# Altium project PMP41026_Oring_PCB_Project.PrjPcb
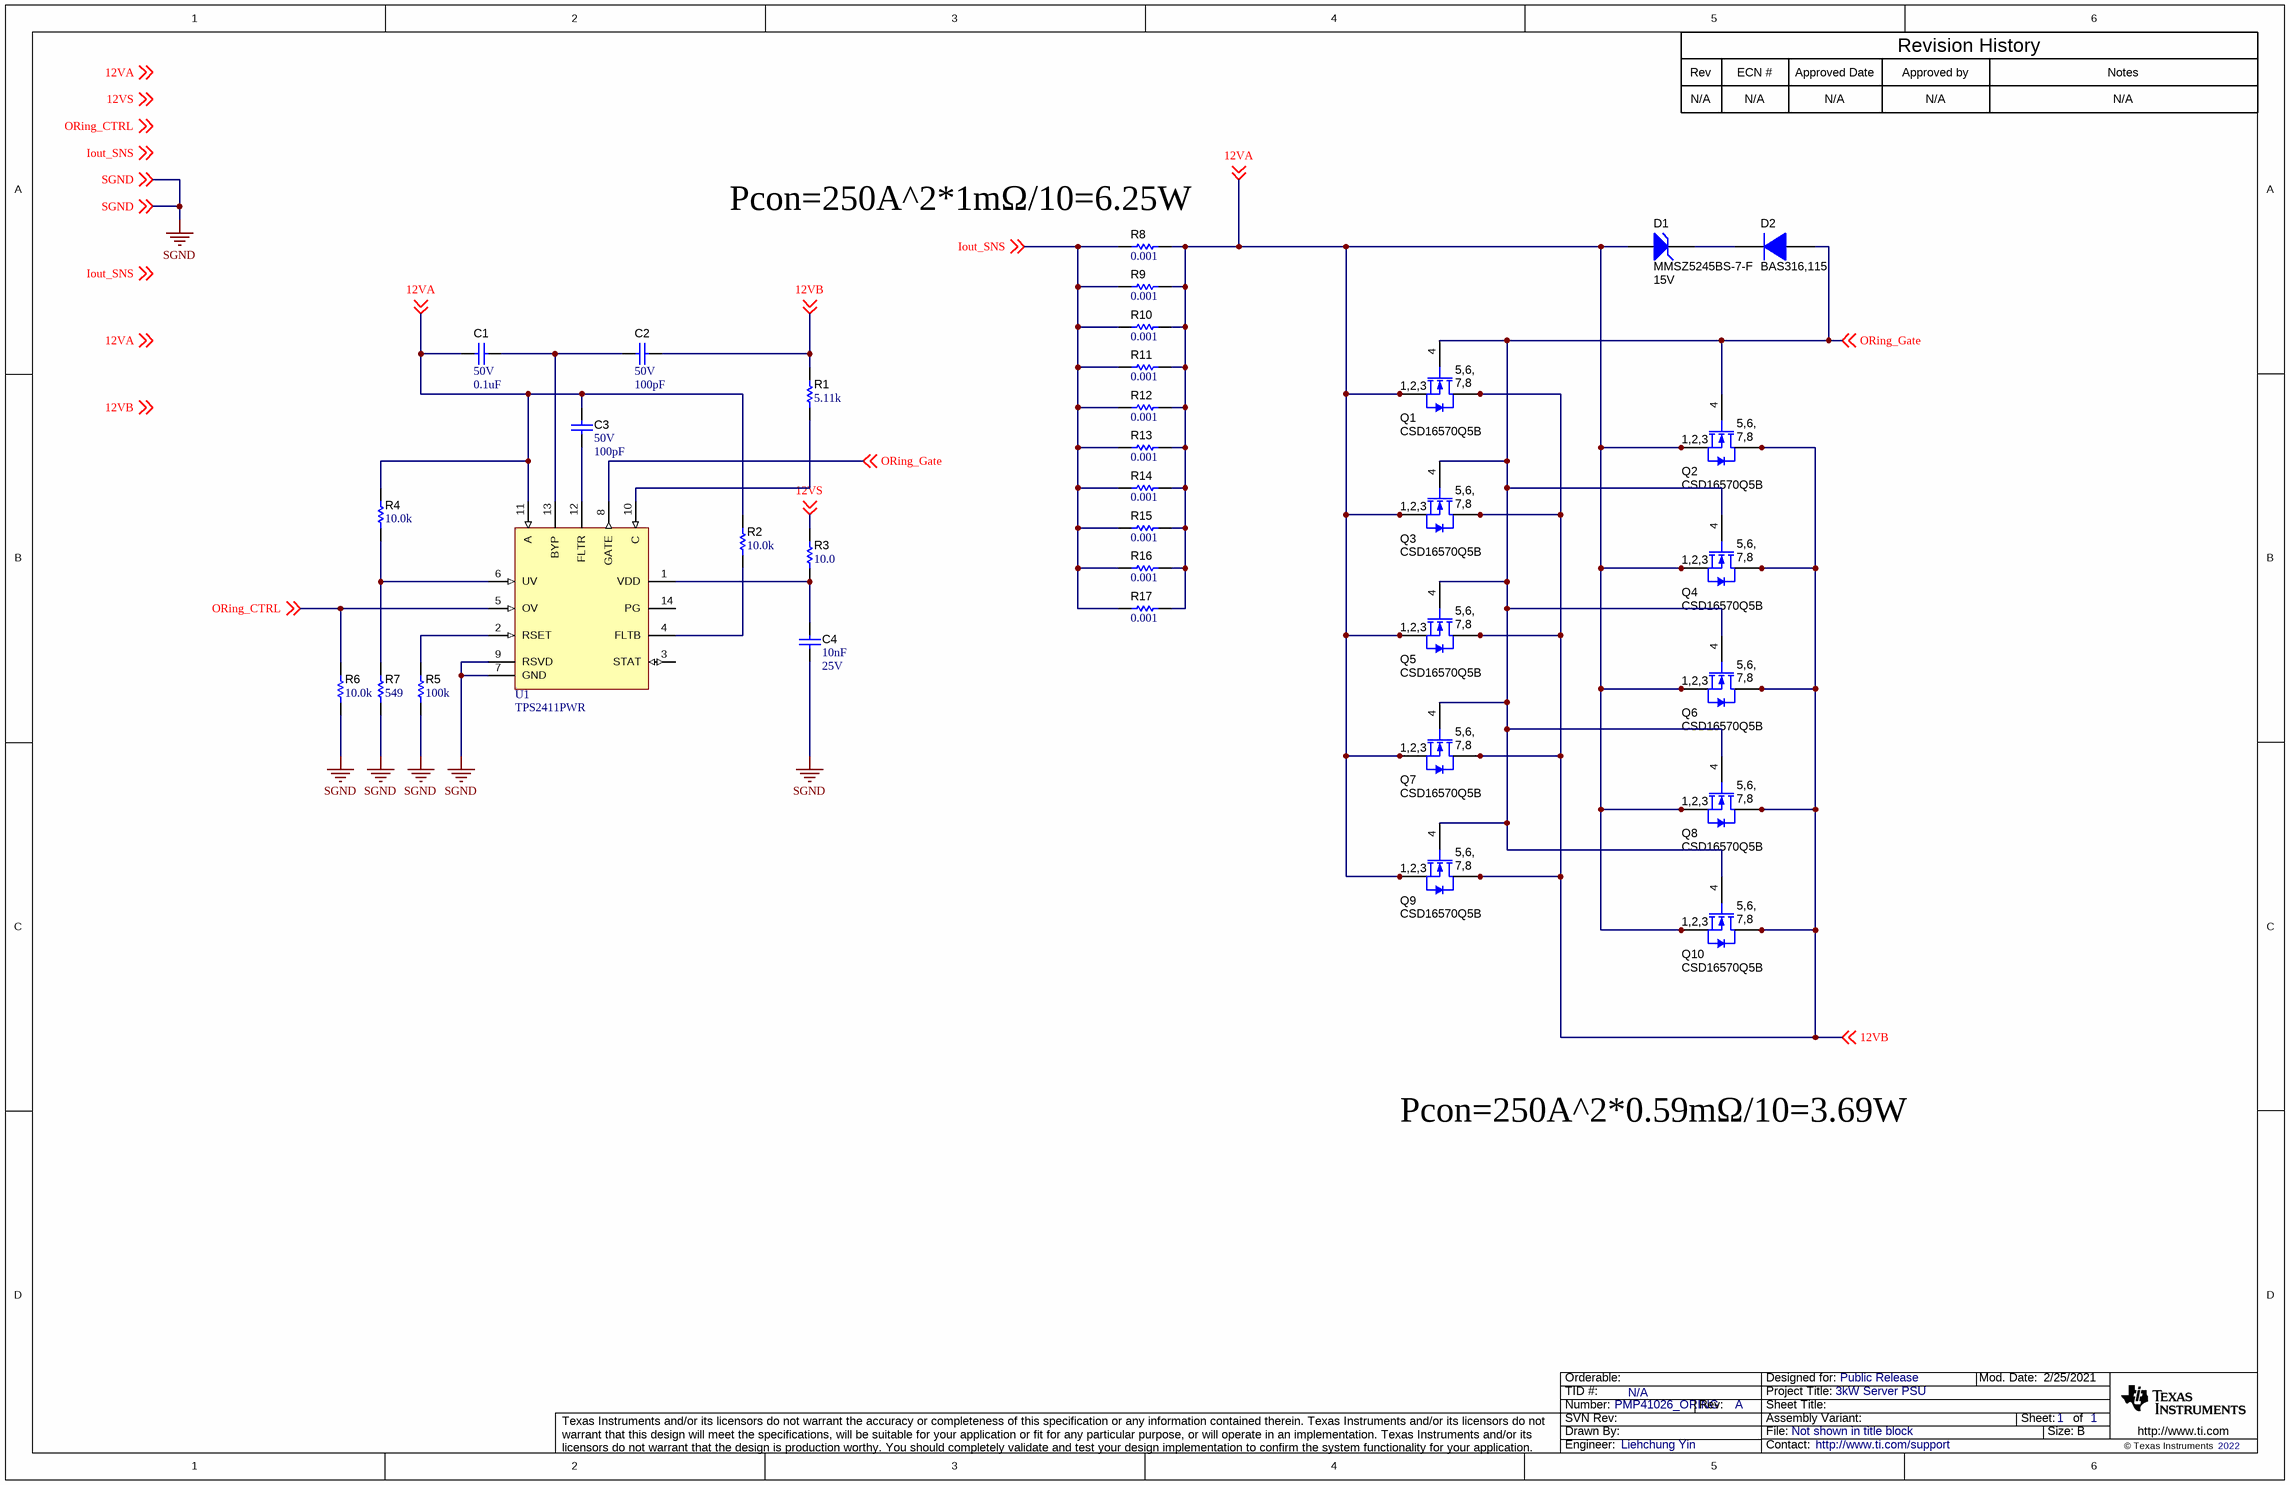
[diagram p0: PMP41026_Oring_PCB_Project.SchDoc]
TID: N/A; TechSupport: http://www.ti.com/support; SCH_Rev: A; PRJ_Title: 3kW Server PSU; PRJ_Number: PMP41026_ORING; PRJ_Engineer: Liehchung Yin; PRJ_Customer: Public Release; PCB_Rev: A; PCB_Layout: B. Lough/S. Yu; CopyrightYear: 2022
1 sheet, 34 parts. Net scope: global (net labels, ports and power ports of the same name join across sheets).
Board file: PMP41026_Oring_PCB_Project.PcbDoc

## Sheet PMP41026_Oring_PCB_Project.SchDoc
size 431 x 279 mm; Date: Not shown in title block; ApprovedBy: Not shown in title block; CheckedBy: Not shown in title block; Author: Not shown in title block; CompanyName: Not shown in title block; Engineer: Not shown in title block; Organization: Not shown in title block; Address1: Not shown in title block; Address2: Not shown in title block; Address3: Not shown in title block; Address4: Not shown in title block; DocumentNumber: 1; Revision: Use project parameter SCH_Rev; SheetNumber: 1; SheetTotal: 1; PageSetup: Record=PageOptions¦CenterHorizontal=True¦CenterVertical=True¦PrintScale=1.00¦XCorrection=1.00¦YCorrection=1.00¦PrintKind=0¦BorderSize=5000000¦LeftOffset=0¦BottomOffset=0¦Orientation=2¦PaperLength=1000¦PaperWidth=1000¦Scale=100¦PaperSource=15¦PrintQuality=600¦MediaType=1¦DitherType=10¦PaperKind=Letter¦PrintScaleMode=1

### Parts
C1  VDC_V: 50V  ValueDisplayed: 0.1uF  [0603L]  (hidden comment: C1608X5R1H104K080AA)
C2  VDC_V: 50V  ValueDisplayed: 100pF  [0603L]  (hidden comment: C0603C101J5GACTU)
C3  VDC_V: 50V  ValueDisplayed: 100pF  [0603L]  (hidden comment: C0603C101J5GACTU)
C4  Cap_F: 10nF  VDC_V: 25V  [0603L]  (hidden comment: GRM188R71E103KA01D)
D1  MMSZ5245BS-7-F  value 15V  [SOD-323]
D2  BAS316,115  [SOD-323]
Q1  CSD16570Q5B  [DNK0008A]
Q2  CSD16570Q5B  [DNK0008A]
Q3  CSD16570Q5B  [DNK0008A]
Q4  CSD16570Q5B  [DNK0008A]
Q5  CSD16570Q5B  [DNK0008A]
Q6  CSD16570Q5B  [DNK0008A]
Q7  CSD16570Q5B  [DNK0008A]
Q8  CSD16570Q5B  [DNK0008A]
Q9  CSD16570Q5B  [DNK0008A]
Q10  CSD16570Q5B  [DNK0008A]
R1  ValueDisplayed: 5.11k  [0402L]  (hidden comment: CRCW04025K11FKED)
R2  ValueDisplayed: 10.0k  [0402L]  (hidden comment: RC0402FR-0710KL)
R3  ValueDisplayed: 10.0  [0402L]  (hidden comment: MCR01MZPF10R0)
R4  ValueDisplayed: 10.0k  [0402L]  (hidden comment: RC0402FR-0710KL)
R5  ValueDisplayed: 100k  [0402L]  (hidden comment: RC0402FR-07100KL)
R6  ValueDisplayed: 10.0k  [0402L]  (hidden comment: RC0402FR-0710KL)
R7  ValueDisplayed: 549  [0402L]  (hidden comment: CRCW0402549RFKED)
R8  ValueDisplayed: 0.001  [WSLP2010-001]  (hidden comment: WSLP20101L000FEA)
R9  ValueDisplayed: 0.001  [WSLP2010-001]  (hidden comment: WSLP20101L000FEA)
R10  ValueDisplayed: 0.001  [WSLP2010-001]  (hidden comment: WSLP20101L000FEA)
R11  ValueDisplayed: 0.001  [WSLP2010-001]  (hidden comment: WSLP20101L000FEA)
R12  ValueDisplayed: 0.001  [WSLP2010-001]  (hidden comment: WSLP20101L000FEA)
R13  ValueDisplayed: 0.001  [WSLP2010-001]  (hidden comment: WSLP20101L000FEA)
R14  ValueDisplayed: 0.001  [WSLP2010-001]  (hidden comment: WSLP20101L000FEA)
R15  ValueDisplayed: 0.001  [WSLP2010-001]  (hidden comment: WSLP20101L000FEA)
R16  ValueDisplayed: 0.001  [WSLP2010-001]  (hidden comment: WSLP20101L000FEA)
R17  ValueDisplayed: 0.001  [WSLP2010-001]  (hidden comment: WSLP20101L000FEA)
U1  TPS2411PWR  [PW0014A_L]

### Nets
SGND: C4.2 R5.1 R6.1 R7.1 U1.7(GND) U1.9(RSVD) ; off-sheet SGND
12VA: C1.2 C3.1 D1.2(A) Q1.1(S) Q1.2(S) Q1.3(S) Q2.1(S) Q2.2(S) Q2.3(S) Q3.1(S) Q3.2(S) Q3.3(S) Q4.1(S) Q4.2(S) Q4.3(S) Q5.1(S) Q5.2(S) Q5.3(S) Q6.1(S) Q6.2(S) Q6.3(S) Q7.1(S) Q7.2(S) Q7.3(S) Q8.1(S) Q8.2(S) Q8.3(S) Q9.1(S) Q9.2(S) Q9.3(S) Q10.1(S) Q10.2(S) Q10.3(S) R2.2 R4.2 R8.2 R9.2 R10.2 R11.2 R12.2 R13.2 R14.2 R15.2 R16.2 R17.2 U1.11(A) ; off-sheet 12VA
12VB: C2.1 Q1.5(D) Q1.6(D) Q1.7(D) Q1.8(D) Q1.9(D) Q2.5(D) Q2.6(D) Q2.7(D) Q2.8(D) Q2.9(D) Q3.5(D) Q3.6(D) Q3.7(D) Q3.8(D) Q3.9(D) Q4.5(D) Q4.6(D) Q4.7(D) Q4.8(D) Q4.9(D) Q5.5(D) Q5.6(D) Q5.7(D) Q5.8(D) Q5.9(D) Q6.5(D) Q6.6(D) Q6.7(D) Q6.8(D) Q6.9(D) Q7.5(D) Q7.6(D) Q7.7(D) Q7.8(D) Q7.9(D) Q8.5(D) Q8.6(D) Q8.7(D) Q8.8(D) Q8.9(D) Q9.5(D) Q9.6(D) Q9.7(D) Q9.8(D) Q9.9(D) Q10.5(D) Q10.6(D) Q10.7(D) Q10.8(D) Q10.9(D) R1.2 ; off-sheet 12VB
12VS: R3.2 ; off-sheet 12VS
Iout_SNS: R8.1 R9.1 R10.1 R11.1 R12.1 R13.1 R14.1 R15.1 R16.1 R17.1 ; off-sheet Iout_SNS
ORing_CTRL: R6.2 U1.5(OV) ; off-sheet ORing_CTRL
ORing_Gate: D2.2(A) Q1.4(G) Q2.4(G) Q3.4(G) Q4.4(G) Q5.4(G) Q6.4(G) Q7.4(G) Q8.4(G) Q9.4(G) Q10.4(G) U1.8(GATE) ; off-sheet ORing_Gate
NetC1_1: C1.1 C2.2 U1.13(BYP)
NetC3_2: C3.2 U1.12(FLTR)
NetC4_1: C4.1 R3.1 U1.1(VDD)
NetD1_1: D1.1(K) D2.1(K)
NetR1_1: R1.1 U1.10(C)
NetR2_1: R2.1 U1.4(FLTB)
NetR4_1: R4.1 R7.2 U1.6(UV)
NetR5_2: R5.2 U1.2(RSET)

Not connected (* = marked no-connect by the designer): U1 3(STAT) 14(PG)

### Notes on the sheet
- Rev
- N/A
- ECN #
- Approved Date
- Approved by
- Revision History
- Notes
- (near R8) Pcon=250A^2*1mΩ/10=6.25W
- Pcon=250A^2*0.59mΩ/10=3.69W
- Labels drawn without touching a wire or pin: 12VA, 12VB, 12VS, Iout_SNS, ORing_CTRL

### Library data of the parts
C1 = CMP-0007010-5: CAP, CERM, 0.1 uF, 50 V, +/- 10%, X5R, 0603; Manufacturer: TDK; TaMin_C: -55°C; ESR_ohm: 0.0296; Polarized: N; SizeAreaWB_mm2: 4.68; Value1: 0.0296 ohm; U/M: EA; Value: 0.1uF; TaMax_C: 85°C; SizeZ_mm: 1; SizeX_mm: 1.6; SizeY_mm: 0.8; Cap_Case: 0603; SizeArea_mm2: 1.28; Cap_F: 100nF; IRMS_A: 9.7199dA; AEC Category: Q200
C2 C3 = CMP-0006841-4: CAP, CERM, 100 pF, 50 V, +/- 5%, C0G/NP0, 0603; Manufacturer: Kemet; TaMin_C: -55°C; Polarized: N; SizeAreaWB_mm2: 4.68; Value1: Unknown; U/M: EA; Value: 100pF; TaMax_C: 125°C; SizeZ_mm: 1; SizeX_mm: 1.6; SizeY_mm: 0.8; Cap_Case: 0603; SizeArea_mm2: 1.28; AEC Category: Q200
C4 = CMP-0007403-4: CAP, CERM, 0.01 uF, 25 V, +/- 10%, X7R, 0603; Manufacturer: MuRata; TaMin_C: -55°C; Polarized: N; SizeAreaWB_mm2: 4.68; Value1: Unknown; U/M: EA; Value: 0.01uF; TaMax_C: 125°C; SizeZ_mm: 1; SizeX_mm: 1.6; SizeY_mm: 0.8; Cap_Case: 0603; SizeArea_mm2: 1.28; AEC Category: Q200
D1 = CMP-0005833-4: Diode, Zener, 15 V, 200 mW, SOD-323; Manufacturer: Diodes Inc.; SizeY_mm: 1.35; RJA_CperW: 350; SizeX_mm: 2.7; AEC Category: Q101; SizeAreaWB_mm2: 8.695; SizeZ_mm: 1; Power_W: 200mW; SizeArea_mm2: 3.645; Value1: 0.2W
D2 = CMP-0029006-2: Diode, Ultrafast, 100 V, 0.25 A, SOD-323; Manufacturer: Nexperia; SizeY_mm: 1.35; Value1: 0.25A; SizeAreaWB_mm2: 8.695; SizeZ_mm: 1; Io_A: 250mA; Value2: 1.4V; SizeX_mm: 2.7; Green_REACh: Incomplete; TJmax_C: 150°C; Green_Lifecycle: Not Set; Vr_V: 100V; AEC Category: Q101; Value: 100V; SizeArea_mm2: 3.645
Q1-Q10 = CMP-0000274-2: MOSFET, N-CH, 25 V, 100 A, DNK0008A (VSON-CLIP-8); Alternate Manufacturer: None; Manufacturer: Texas Instruments; SizeZ_mm: 1; ChType: N; Value2: 192 nC; Value1: 0; VdsMax_V: 25V; SizeX_mm: 6; SizeY_mm: 5; Vgs_V: 20V; Value: 25V; Rdson45_ohm: 800µ; SizeArea_mm2: 30; AEC Category: Q101; IdsMax_A: 100A; SizeAreaWB_mm2: 56; U/M: EA; QgTyp_nC: 192
R1 = CMP-0026463-2: RES, 5.11 k, 1%, 0.063 W, AEC-Q200 Grade 0, 0402; Manufacturer: Vishay-Dale; Power_W: 63mW; TempCo: 100 ppm/C; Value_Code: 5k11; Value: 5.11k; EIA_Code: E96; SizeX_mm: 1; SizeY_mm: 0.5; SizeZ_mm: 0.6; Value2: 0.063W; AEC Qualified: Y; VDC_V: 50V; AEC Category: Q200; AEC Grade: 0
R2 R4 R6 = CMP-0078669-1: RES, 10.0 k, 1%, 0.063 W, 0402; Manufacturer: Yageo America; Power_W: 63mW; Green_Lifecycle: Active; TempCo: 100 ppm/C; Value_Code: 10k0; Green_REACh: Passed; Value: 10.0k; EIA_Code: E96; Res_ohm: 10k; SizeX_mm: 1; SizeY_mm: 0.5; SizeZ_mm: 0.6; Value2: 0.063W; AEC Qualified: N; AEC Category: Q200
R3 = CMP-0026717-1: RES, 10.0, 1%, 0.063 W, 0402; Manufacturer: Rohm; Power_W: 63mW; TempCo: 100 ppm/C; Value_Code: 10R0; U/M: EA; Value: 10.0; EIA_Code: E96; Res_ohm: 10; SizeX_mm: 1; SizeY_mm: 0.5; SizeZ_mm: 0.6; Value2: 0.063W; AEC Qualified: N; VDC_V: 50V; AEC Category: Q200
R5 = CMP-0026721-1: RES, 100 k, 1%, 0.0625 W, 0402; Manufacturer: Yageo America; Power_W: 62.5mW; TempCo: 100 ppm/C; U/M: EA; Value: 100k; EIA_Code: E96; SizeX_mm: 1; SizeY_mm: 0.5; SizeZ_mm: 0.6; AEC Qualified: N; VDC_V: 50V; AEC Category: Q200
R7 = CMP-0026448-2: RES, 549, 1%, 0.063 W, AEC-Q200 Grade 0, 0402; Manufacturer: Vishay-Dale; Power_W: 63mW; TempCo: 100 ppm/C; Value_Code: 549R; Value: 549; EIA_Code: E96; SizeX_mm: 1; SizeY_mm: 0.5; SizeZ_mm: 0.6; Value2: 0.063W; AEC Qualified: Y; VDC_V: 50V; AEC Category: Q200; AEC Grade: 0
R8-R17 = CMP-0016564-3: RES, 0.001, 1%, 2 W, 2010; Manufacturer: Vishay-Dale; Value2: 2W; SizeX_mm: 5.08; SizeY_mm: 2.54; SizeZ_mm: 0.89; AEC Qualified: N; Value: 0.001; SizeArea_mm2: 12.9032; AEC Category: Q200; U/M: EA; TempCo: 275 ppm/C; Value_Code: 1L000; EIA_Code: E96; Res_ohm: 1m
U1 = CMP-0038282-1: N+1 and OR-ing Power Rail Controller, 0.8 to 16.5 V, -40 to 85 degC, 14-pin TSSOP (PW), Green (RoHS & no Sb/Br); Manufacturer: Texas Instruments; Fault and Status: Yes; Vin(Min)(V): 0.8; Gate Control: on/off; No. of Outputs: 1; Vin(Max)(V): 16.5

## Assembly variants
001: not fitted FID1 FID2 FID3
